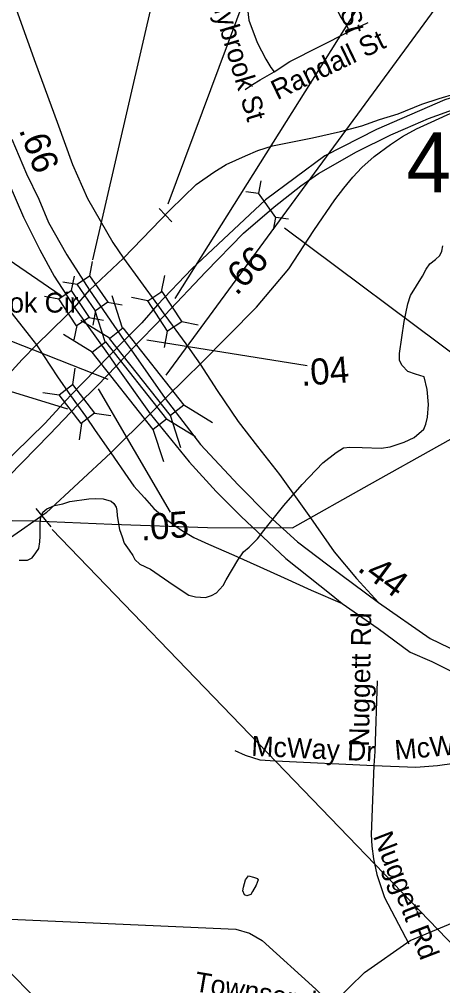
# Model space of a CAD drawing. Extents: x 1662474 to 1856135, y 779280 to 917889.
# Drawn here: x 1711717 to 1713744, y 797474 to 802097 of the extents above; entities that cross this region are included whole.
import ezdxf

# ---------------------------------------------------------------- set-up
doc = ezdxf.new("R2010")
doc.units = 0
for name, color, linetype in [('Cogo Default Point CELL', 7, 'Continuous'), ('Exist Hydrographic Creek Single Shore', 7, 'Continuous'), ('Exist Hydrographic Misc Water Feature', 7, 'Continuous'), ('Exist Road Non-System Structure Non-Sys NCDOT Number Label', 7, 'Continuous'), ('Exist Road Non-System Type 51', 7, 'Continuous'), ('Exist Road Non-System Type 51 Label', 7, 'Continuous'), ('Exist Road Primary Interstate Divided Center Attributed', 7, 'Continuous'), ('Exist Road Primary Interstate Mileage Hundredths English Label', 7, 'Continuous'), ('Exist Road Primary Interstate Ramp 1 Lane Attributed', 7, 'Continuous'), ('Exist Road Primary Interstate Structure Culvert CELL', 7, 'Continuous'), ('Exist Road Primary Interstate Structure Culvert Number Label', 7, 'Continuous'), ('Exist Road Primary Interstate Structure Ovrhead Sign CELL', 7, 'Continuous'), ('Exist Road Primary US Divided Attributed', 7, 'Continuous'), ('Exist Road Primary US Mileage Hundredths English Label', 7, 'Continuous'), ('Exist Road Primary US Ramp 1 Lane  Attributed', 7, 'Continuous'), ('Exist Road Primary US Structure Standard Bridge CELL', 7, 'Continuous'), ('Exist Road Secondary Type 51 Attributed', 7, 'Continuous'), ('Exist Utilities Electrical Transmission Line', 7, 'Continuous'), ('Scratch_Level_2', 7, 'Continuous')]:
    doc.layers.add(name, color=color, linetype=linetype)

msp = doc.modelspace()

# ---------------------------------------------------------------- linework, layer by layer
at = {"layer": 'Exist Hydrographic Creek Single Shore'}
for points in [[(1713559, 800650.6), (1713576.9, 800735.9), (1713590.2, 800776.3), (1713647.2, 800868.2), (1713664.2, 800901.5), (1713683.1, 800927.5), (1713709.1, 800947.8), (1713729.9, 800967.1), (1713740.6, 800987.4), (1713744.6, 801013.6)], [(1711715.8, 799509.2), (1711755.9, 799508.9), (1711779, 799521), (1711797.1, 799544.1), (1711810.5, 799565.9), (1711816, 799597.9), (1711817.6, 799623.9), (1711817.4, 799675.3), (1711819.1, 799708.9), (1711829.4, 799739.6), (1711848.4, 799755.1), (1711885.9, 799771.1), (1711924.8, 799779.8), (1711958.8, 799790.5), (1712050.1, 799802.3), (1712084.2, 799805.2), (1712118.4, 799803.6), (1712157.2, 799791.3), (1712170.4, 799781.1), (1712181.1, 799763.8), (1712184, 799746.4), (1712186.4, 799723.3), (1712189.8, 799692.4), (1712196.9, 799656.7), (1712208.9, 799621.2), (1712219.1, 799590.8), (1712243.9, 799556.9), (1712260.4, 799531.5), (1712270.4, 799512.6), (1712293.5, 799491.1), (1712344.9, 799465.9), (1712453.2, 799391.3), (1712528.4, 799342.5), (1712560.1, 799334.1), (1712608.6, 799331.2), (1712637.8, 799340.4), (1712660.9, 799353), (1712676.1, 799369.6), (1712693.1, 799387.9), (1712707.6, 799415.8), (1712763, 799508.9), (1712790.2, 799549.3), (1712817, 799572.4), (1712857, 799611.2), (1712888.2, 799651.4), (1712983.2, 799771.4), (1713070.9, 799871.6), (1713170.9, 799974.8), (1713234.1, 800024.6), (1713269.5, 800046.9), (1713299.2, 800049.8), (1713358.2, 800048.5), (1713448.8, 800044.9), (1713492.6, 800051.7), (1713559, 800074), (1713607.4, 800096.8), (1713654.4, 800135.7), (1713663.8, 800160.6), (1713671.9, 800194.2), (1713676.1, 800254.1), (1713670.4, 800326.2), (1713654.9, 800386.6), (1713613.6, 800399.2), (1713577.1, 800411.5), (1713550.4, 800441.4), (1713537.5, 800464.8), (1713537.5, 800498.6), (1713559, 800650.6)]]:
    msp.add_lwpolyline(points, dxfattribs=at)
at = {"layer": 'Exist Hydrographic Misc Water Feature'}
msp.add_lwpolyline([(1712856.5, 797986.5), (1712860.5, 797980.5), (1712850.3, 797954.6), (1712833.9, 797924.7), (1712825.8, 797910.8), (1712805.8, 797903), (1712795.7, 797909.1), (1712788, 797927.2), (1712790.1, 797945.1), (1712800.6, 797981), (1712814.6, 797998.9), (1712838.7, 797992.7), (1712852.5, 797988.5), (1712856.5, 797986.5)], dxfattribs=at)
msp.add_lwpolyline([(1712856.5, 797986.5), (1712860.5, 797980.5), (1712850.3, 797954.6), (1712833.9, 797924.7), (1712825.8, 797910.8), (1712805.8, 797903), (1712795.7, 797909.1), (1712788, 797927.2), (1712790.1, 797945.1), (1712800.6, 797981), (1712814.6, 797998.9), (1712838.7, 797992.7), (1712852.5, 797988.5), (1712856.5, 797986.5)], dxfattribs=at)
at = {"layer": 'Exist Road Non-System Structure Non-Sys NCDOT Number Label'}
msp.add_line((1710361.9, 798852.7), (1713642, 795560.3), dxfattribs=at)
at = {"layer": 'Exist Road Non-System Type 51'}
msp.add_line((1713296.9, 802038), (1713387.6, 802082.6), dxfattribs=at)
for points in [[(1712824.1, 802634.9), (1712813.9, 802583.4), (1712809.9, 802375.5), (1712801.9, 802216.2), (1712815.8, 802092.6), (1712856.1, 801985.5), (1712896.9, 801906.8), (1712921, 801866.1), (1712937.2, 801845.4)], [(1713150.6, 802627.8), (1713151.1, 802411.8), (1713169.2, 802300.4), (1713197.4, 802223.8), (1713258.2, 802104.7), (1713286.6, 802062.4), (1713296.9, 802038)], [(1712937.2, 801845.4), (1713012.1, 801894.7), (1713296.9, 802038)], [(1712798.9, 801760.8), (1712833.4, 801785.8), (1712870.9, 801807.7), (1712937.2, 801845.4)], [(1713430.9, 798931.8), (1713418.9, 798593.7), (1713414.1, 798527.5)], [(1712749.1, 798599.4), (1712798.9, 798576.1), (1712868, 798555.1), (1712943.6, 798549.4), (1713414.1, 798527.5)], [(1713414.1, 798527.5), (1713615.4, 798519.4), (1713718.6, 798527), (1713867.4, 798547.8), (1713939.9, 798569.8)], [(1713414.1, 798527.5), (1713401.6, 798197.4), (1713404.4, 798140.7), (1713412.1, 798081.4), (1713428.1, 798005), (1713465.9, 797895), (1713582.6, 797674)], [(1710395.4, 797648), (1710891.9, 797708.2), (1711070.4, 797733.4), (1711247.2, 797781.6), (1711320.8, 797795.8), (1711395.2, 797801.9), (1711564.4, 797796.9), (1712753, 797744.4), (1712818.4, 797725.2), (1712880, 797690.2), (1713136.8, 797457.8), (1713219.4, 797377.2)]]:
    msp.add_lwpolyline(points, dxfattribs=at)
at = {"layer": 'Exist Road Primary Interstate Divided Center Attributed'}
for points in [[(1714009.7, 801788.4), (1713987.1, 801782.1), (1713886.6, 801752.9), (1713753.5, 801712.3), (1713426.7, 801569.7), (1713179, 801444.7), (1712895.9, 801234.2), (1712542.6, 800904.1), (1712379.1, 800731.1)], [(1712414.6, 800682), (1712609.4, 800888.2), (1712791.1, 801074.6), (1712937.2, 801199.5), (1713064.7, 801300.9), (1713149.5, 801359.7), (1713331.3, 801463.1), (1713495.6, 801544.3), (1713565.9, 801575.5), (1713676.1, 801622.5), (1713812.7, 801672.7), (1713918.5, 801704.2)], [(1712379.1, 800731.1), (1712303.9, 800645.7), (1712219.2, 800560.8)], [(1712252.6, 800515.2), (1712414.6, 800682)], [(1712219.2, 800560.8), (1712146.8, 800486.6)], [(1712181.6, 800437.6), (1712252.6, 800515.2)], [(1712146.8, 800486.6), (1711962.9, 800297.9)], [(1711996, 800251.2), (1712090.9, 800344.7), (1712181.6, 800437.6)], [(1711962.9, 800297.9), (1711840.3, 800165.1), (1711618.7, 799949.1), (1711493.1, 799810.4), (1711275.7, 799607.7), (1711165.1, 799518.4), (1710981.7, 799381.1), (1710923, 799346.3), (1710867.1, 799312.1)], [(1710251, 798879.9), (1710596.4, 799077.3), (1710686, 799131.7), (1710777.2, 799182.9), (1710858.8, 799235.7), (1710940.3, 799290.9), (1711004.5, 799331.5), (1711120.2, 799414), (1711200.4, 799477.7), (1711421.6, 799661.7), (1711598.3, 799843.2), (1711863.3, 800113), (1711996, 800251.2)]]:
    msp.add_lwpolyline(points, dxfattribs=at)
at = {"layer": 'Exist Road Primary Interstate Mileage Hundredths English Label'}
for p, q in [((1712327.3, 800563.4), (1713094.5, 800441.2)), ((1712095.4, 800328.8), (1712439.8, 799739.8))]:
    msp.add_line(p, q, dxfattribs=at)
at = {"layer": 'Exist Road Primary Interstate Ramp 1 Lane Attributed'}
for p, q in [((1712053.7, 800800.5), (1712215.6, 800953.8)), ((1711981.5, 800718.1), (1712053.7, 800800.5)), ((1712344.4, 800209.9), (1712415.7, 800283)), ((1712155.8, 800023.5), (1712344.4, 800209.9))]:
    msp.add_line(p, q, dxfattribs=at)
for points in [[(1712215.6, 800953.8), (1712439.3, 801185.7), (1712563.9, 801307), (1712648, 801366.1), (1712708.1, 801402.9), (1712800, 801444.1), (1712858.7, 801469.4), (1712930, 801491.6), (1713017.2, 801509), (1713120.3, 801529.6), (1713255.2, 801560.7), (1713356.3, 801587.2), (1713442.1, 801617.4), (1713531, 801644.5), (1713644.3, 801690.8), (1713727.8, 801718.8), (1713876.3, 801762.2), (1714009.7, 801788.4)], [(1712583.5, 800447.1), (1712852.4, 800719.6), (1713007.2, 800903.3), (1713126.5, 801087), (1713228.3, 801232.9), (1713270.4, 801289.4), (1713313.8, 801342), (1713357.2, 801388), (1713416.4, 801440.6), (1713494, 801498.5), (1713551.7, 801536.3), (1713618.4, 801573.7), (1713688.7, 801604.8), (1713765.1, 801640.3), (1713918.5, 801704.2)], [(1711799.4, 800539.8), (1711941.2, 800678.4), (1711981.5, 800718.1)], [(1711489.5, 800114.1), (1711584.3, 800280.9), (1711604.4, 800312.1), (1711639.4, 800364.4), (1711683.1, 800416.9), (1711730.5, 800469.3), (1711799.4, 800539.8)], [(1712415.7, 800283), (1712517.1, 800383.7), (1712583.5, 800447.1)], [(1712155.8, 800023.5), (1711845.3, 799735.8), (1711727.9, 799653.8), (1711512.9, 799504.8)]]:
    msp.add_lwpolyline(points, dxfattribs=at)
at = {"layer": 'Exist Road Primary Interstate Structure Culvert CELL'}
for p, q in [((1712872.9, 801324.9), (1712861.7, 801265.8)), ((1712802.1, 801273.8), (1712861.7, 801265.8)), ((1712945.6, 801149.6), (1712861.7, 801265.8)), ((1712934.4, 801090.4), (1712945.6, 801149.6)), ((1713005.2, 801141.6), (1712945.6, 801149.6))]:
    msp.add_line(p, q, dxfattribs=at)
at = {"layer": 'Exist Road Primary Interstate Structure Culvert Number Label'}
msp.add_line((1712986.3, 801099.1), (1714779.6, 799760), dxfattribs=at)
at = {"layer": 'Exist Road Primary Interstate Structure Ovrhead Sign CELL'}
for p, q in [((1712430.6, 801213.7), (1714482.1, 806737.8)), ((1712386.2, 801191.3), (1712447.9, 801127.8)), ((1711796.1, 799756), (1711868.8, 799668.4)), ((1711874.2, 799656.4), (1714941.8, 796476.9))]:
    msp.add_line(p, q, dxfattribs=at)
at = {"layer": 'Exist Road Primary US Divided Attributed'}
for p, q in [((1712053.7, 800800.5), (1712219.2, 800560.8)), ((1711981.5, 800718.1), (1712146.8, 800486.6)), ((1712219.2, 800560.8), (1712252.6, 800515.2)), ((1712252.6, 800515.2), (1712415.7, 800283)), ((1712146.8, 800486.6), (1712181.6, 800437.6)), ((1712181.6, 800437.6), (1712344.4, 800209.9))]:
    msp.add_line(p, q, dxfattribs=at)
for points in [[(1711681.4, 801524.1), (1711752.4, 801358.4), (1711810, 801236.9), (1711857.4, 801125.2), (1711944, 800970.6), (1712053.7, 800800.5)], [(1711666.7, 801313.5), (1711736.7, 801150.9), (1711815.1, 800994.1), (1711884.2, 800868.7), (1711981.5, 800718.1)], [(1712415.7, 800283), (1712583.8, 800063.1), (1712764.1, 799869.8), (1712911.6, 799722.4), (1713049.2, 799597.9), (1713193.5, 799486.5), (1713436.3, 799306.8)], [(1712344.4, 800209.9), (1712530.1, 799980.6), (1712659.9, 799838.1), (1712779.6, 799718.5), (1712937.4, 799570.9), (1712993.4, 799517.5), (1713209.9, 799345.6), (1713262.6, 799302.3)], [(1713262.6, 799302.3), (1713434.8, 799182.2), (1713587.9, 799069.8), (1713692.3, 799024.8), (1713860.5, 798940.7), (1714051.7, 798842.9), (1714287.3, 798724.2)], [(1713436.3, 799306.8), (1713683.9, 799134.5), (1713997.7, 798983.1), (1714306.7, 798826.7)]]:
    msp.add_lwpolyline(points, dxfattribs=at)
at = {"layer": 'Exist Road Primary US Ramp 1 Lane  Attributed'}
for p, q in [((1712215.6, 800953.8), (1712379.1, 800731.1)), ((1712379.1, 800731.1), (1712414.6, 800682)), ((1711962.9, 800297.9), (1711996, 800251.2))]:
    msp.add_line(p, q, dxfattribs=at)
for points in [[(1711531.9, 802624.8), (1711583, 802474.9), (1711672.1, 802231.7), (1711794.1, 801887.9), (1711897.7, 801605.3), (1711971.2, 801402.4), (1712043.2, 801239.1), (1712165.6, 801028.7), (1712215.6, 800953.8)], [(1711137.8, 802076.8), (1711127.4, 801941.8), (1711129, 801858.5), (1711139.8, 801736.6), (1711169.1, 801600.8), (1711215.4, 801458.8), (1711247.8, 801375.5), (1711280.8, 801303.8), (1711320, 801225.4), (1711390.7, 801117.2), (1711466, 801002.7), (1711522.5, 800925.9), (1711630, 800755.7), (1711765.2, 800584.7), (1711799.4, 800539.8)], [(1712414.6, 800682), (1712514.2, 800544.5), (1712583.5, 800447.1)], [(1711799.4, 800539.8), (1711900, 800387.2), (1711962.9, 800297.9)], [(1712583.5, 800447.1), (1712664.3, 800321.5), (1712764.6, 800173.5), (1712857.6, 800053.4), (1712962, 799919.7), (1713110.6, 799712.2), (1713224, 799549), (1713331.1, 799421.6), (1713436.3, 799306.8)], [(1711996, 800251.2), (1712034.6, 800198.9), (1712081, 800129.3), (1712155.8, 800023.5)], [(1712155.8, 800023.5), (1712236.7, 799904.9), (1712266, 799864.2), (1712316.7, 799807.4), (1712361.4, 799756), (1712395.8, 799726.8), (1712427.6, 799700.1), (1712493.6, 799653.3), (1712552.4, 799618.7), (1712623.1, 799586.6), (1712743.4, 799533.2), (1712869.4, 799477.8), (1712985.8, 799424.4), (1713113.7, 799365.3), (1713262.6, 799302.3)]]:
    msp.add_lwpolyline(points, dxfattribs=at)
at = {"layer": 'Exist Road Primary US Structure Standard Bridge CELL'}
for p, q in [((1712065.5, 800939.2), (1712052.9, 800870.2)), ((1711979.6, 800867.9), (1711965.8, 800799.1)), ((1712398.3, 800793.4), (1712414.2, 800871)), ((1711924.9, 800841.8), (1711993.9, 800829.3)), ((1711837.3, 800773), (1711906.1, 800759.3)), ((1712211.5, 800620), (1712161.3, 800774.1)), ((1712332.2, 800749.8), (1712254.6, 800765.7)), ((1712140.1, 800743.6), (1712209.2, 800731)), ((1712082.4, 800703.7), (1712069.9, 800634.6)), ((1712128.9, 800553.4), (1712078.6, 800707.4)), ((1711992.4, 800632.1), (1711978.6, 800563.3)), ((1712149.3, 800570.9), (1712011.2, 800655.6)), ((1712050.8, 800671), (1712119.6, 800657.3)), ((1712572.7, 800633.4), (1712495.1, 800649.3)), ((1712066.7, 800504.3), (1711928.5, 800588.9)), ((1712411.5, 800527.1), (1712427.4, 800604.7)), ((1711982.8, 800428.8), (1711972.2, 800350.3)), ((1711829.3, 800311.6), (1711907.8, 800301.1)), ((1712077.2, 800212.2), (1712155.8, 800201.6)), ((1712642.7, 800166.6), (1712504.5, 800251.3)), ((1712560.1, 800100), (1712421.9, 800184.6)), ((1712491.1, 800047), (1712440.9, 800201)), ((1712014.3, 800164.1), (1712003.7, 800085.5)), ((1712408.5, 799980.3), (1712358.3, 800134.4))]:
    msp.add_line(p, q, dxfattribs=at)
for points in [[(1712052.9, 800870.2), (1712140.4, 800743.8), (1712081.4, 800702.9), (1711993.9, 800829.3)], [(1711965.8, 800799.1), (1712051.1, 800671.2), (1711991.3, 800631.4), (1711906.1, 800759.3)], [(1712427.4, 800604.7), (1712331.9, 800749.6), (1712399.5, 800794.2), (1712495.1, 800649.3)], [(1712440.9, 800201), (1712149, 800570.7), (1712212.7, 800620.9), (1712504.5, 800251.3)], [(1712358.3, 800134.4), (1712066.4, 800504.1), (1712130, 800554.3), (1712421.9, 800184.6)], [(1711972.2, 800350.3), (1712077.5, 800212.4), (1712013.1, 800163.2), (1711907.8, 800301.1)]]:
    msp.add_lwpolyline(points, close=True, dxfattribs=at)
at = {"layer": 'Exist Road Secondary Type 51 Attributed'}
msp.add_lwpolyline([(1711980.1, 792720.4), (1712057.3, 793192.1), (1712117.7, 793573.1), (1712168.9, 793949.6), (1712234, 794372.5), (1712271.2, 794651.3), (1712289.2, 794759), (1712329.2, 794912.6), (1712473.9, 795357.1), (1712559.9, 795520.4), (1712593.7, 795605.5), (1712625.8, 795705.1), (1712648.3, 795803), (1712674.7, 795925.5), (1712699.3, 796156.8), (1712781.9, 796663.3), (1712836.2, 796867.3), (1712887.2, 796972.5), (1712944.6, 797071.4), (1713225.3, 797396.5), (1713368.9, 797536.8), (1713589, 797689.8), (1713974.4, 797851.7), (1714335.6, 798017.4)], dxfattribs=at)
at = {"layer": 'Exist Utilities Electrical Transmission Line'}
msp.add_lwpolyline([(1711475, 799701.9), (1711785.1, 799697.6), (1712160.6, 799682.4), (1712618.5, 799666.2), (1713024.5, 799664.8), (1713393.1, 799871.3), (1714066.4, 800247.9), (1714582.3, 800534.5), (1715172.6, 800864.2), (1715751.6, 800927.9), (1716296.5, 800994.3), (1716760.9, 801042), (1717113.7, 801085), (1717368, 801115.3), (1718163.6, 801226.5), (1718770.7, 801313.9), (1719216.9, 801191.9)], dxfattribs=at)
at = {"layer": 'Scratch_Level_2'}
for p, q in [((1712463.9, 800761), (1716241.1, 806773)), ((1712068.6, 800946.6), (1713292.3, 806225.4)), ((1712420.6, 800394.1), (1715864.4, 805083.3)), ((1711912.3, 800777.1), (1708764.4, 802936)), ((1712142.7, 800374.6), (1708390.3, 801846.8)), ((1711949, 800232.2), (1708093.7, 801424))]:
    msp.add_line(p, q, dxfattribs=at)

# ---------------------------------------------------------------- texts
at = {"layer": 'Cogo Default Point CELL'}
msp.add_text('4060', height=288, dxfattribs=at).set_placement((1713570.3, 801269))
at = {"layer": 'Exist Road Non-System Type 51 Label'}
for s, rotation, p in [('Randall St', 283.5283, (1713144, 802592.5)), ('Sunnybrook St', 286.6734, (1712571, 802400.4)), ('Randall St', 25.809, (1712951.7, 801709.5)), ('Nuggett Rd', 88.9397, (1713390.7, 798616.6)), ('McWay Dr', 5.2625, (1713518, 798553.2)), ('McWay Dr', 357.4002, (1712826.6, 798573.7)), ('Nuggett Rd', 291.0335, (1713409.9, 798189.3)), ('Townsend Ave', 350.3058, (1712551.1, 797448.1))]:
    msp.add_text(s, height=95, rotation=rotation, dxfattribs=at).set_placement(p)
msp.add_text('Mossbrook Cir', height=95, dxfattribs=at).set_placement((1711182, 800694))
at = {"layer": 'Exist Road Primary Interstate Mileage Hundredths English Label'}
for s, rotation, p in [('.66', 45.7493, (1712756.7, 800770.7)), ('.04', 4.5809, (1713068.5, 800342.6)), ('.05', 4.3982, (1712301.4, 799603.1))]:
    msp.add_text(s, height=125, rotation=rotation, dxfattribs=at).set_placement(p)
at = {"layer": 'Exist Road Primary US Mileage Hundredths English Label'}
for s, rotation, p in [('.66', 290.3505, (1711714.2, 801568.3)), ('.44', 323.4838, (1713331, 799462.5))]:
    msp.add_text(s, height=125, rotation=rotation, dxfattribs=at).set_placement(p)

doc.saveas('drawing.dxf')
